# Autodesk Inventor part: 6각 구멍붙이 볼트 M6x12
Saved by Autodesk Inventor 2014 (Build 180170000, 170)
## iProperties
Created: 2026-05
Part Number: 6각 구멍붙이 볼트 M6x12
Material: 일반
Document SubType Name: Modeling
Designer: dg
Density: 1 g/cm^3
Appearance: 기본값
Author: dg
Author: jhkim
Description: 6각머리 태핑 나사
Creation Date: 2026-04-23
Sending System: Autodesk Inventor 2027
Preprocessor: ST-DEVELOPER v20.1
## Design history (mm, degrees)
node "6각 구멍붙이 볼트 M6x121"
body "Solid1"
node "기준1"
